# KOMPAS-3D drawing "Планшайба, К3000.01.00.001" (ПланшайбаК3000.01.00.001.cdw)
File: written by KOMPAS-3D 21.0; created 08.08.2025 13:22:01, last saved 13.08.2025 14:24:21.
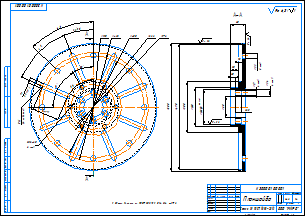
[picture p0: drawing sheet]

Sheet 1: A2, landscape

Document properties: Автор: admin; Знак неуказанной шероховатости: 4; Параметр неуказанной шероховатости: Ra 6,3; Масса: 24.201198; Полное имя файла: ..\Из трубы\Планшайба.m3d

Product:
- Part/product: Планшайба  | designation К3000.01.00.001
    Материал: Сталь 45 ГОСТ 1050-2013 (density 7810 kg/m3)
    Масса: 24.201198

Title block, sheet 1: Наименование: Планшайба; designation: К3000.01.00.001; Материал: Сталь 35 ГОСТ 1050-2013; Масса: 24,2; Количество листов документа: 1; organisation: ООО "МИРО"; Форматы листов документа: A2; stored path: C:\Users\ShavarinML\Desktop\Стапель\2D\ПланшайбаК3000.01.00.001.cdw

Views: Проекционный вид 2, Разрез А-А
Referenced files in C:\Users\ShavarinML\Desktop\Стапель\Из трубы\: Планшайба.m3d
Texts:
  Ra 3,2
  Ra 1,6
  Ra 6,3
  Ra 6,3 ( )
  К3000.01.00.001 Планшайба
Dimensions and other numbers on the sheet: 428; 400; 222; 176; 110; 22 30'; 22; 8 пазов; 103; -6H; 16; 6 отв.; 11; 16 радиусов; 500; 490; 200; 150; 135; 80; 26; 17; 20; 30; 15; 60; 8 отв.; 22,5; 1:4; 1; 24,2

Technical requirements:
  Общие допуски по ГОСТ 30893.1: H14, h14,   IT/2.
